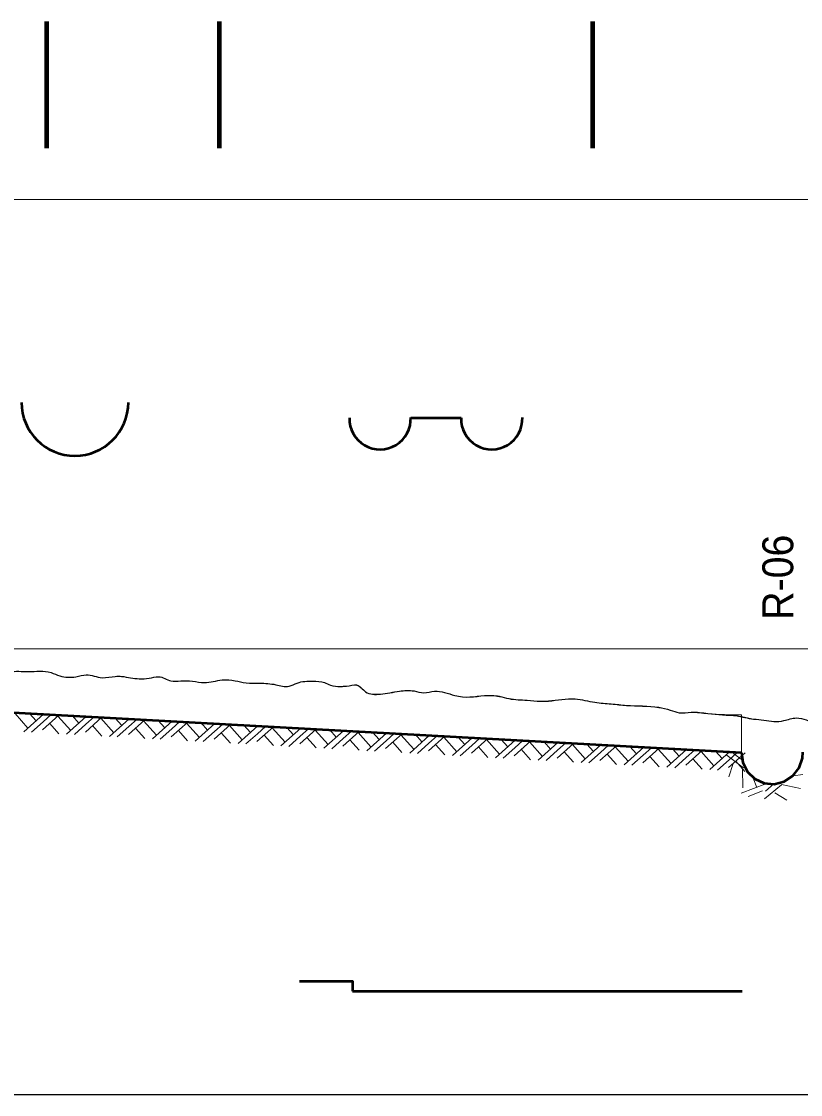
# Model space of a CAD drawing. Extents: x 8458 to 9360, y 19921 to 20366.
# Drawn here: x 8665.8 to 8766.6, y 20102.6 to 20241.4 of the extents above; entities that cross this region are included whole.
import ezdxf

# ---------------------------------------------------------------- set-up
doc = ezdxf.new("R2010")
doc.units = 0
doc.header["$LTSCALE"] = 1.2
doc.layers.add('5', color=7, linetype='Continuous', lineweight=13)

msp = doc.modelspace()

# ---------------------------------------------------------------- linework, layer by layer
at = {"layer": '5', "lineweight": 90}
for p, q in [((8669.04, 20225.05), (8669.04, 20241.43)), ((8691.42, 20225.05), (8691.42, 20241.43)), ((8739.72, 20225.05), (8739.72, 20241.43))]:
    msp.add_line(p, q, dxfattribs=at)
at = {"layer": '5'}
for p, q in [((8509.89, 20218.4), (9341.84, 20218.4)), ((8509.89, 20160.27), (9341.84, 20160.27)), ((8664.94, 20151.87), (8666.61, 20150)), ((8668.62, 20151.81), (8666.07, 20149.52)), ((8666.82, 20151.9), (8667.67, 20150.95)), ((8670.63, 20151.69), (8668.51, 20149.79)), ((8669.63, 20151.75), (8668.57, 20150.8)), ((8670.49, 20151.56), (8672.16, 20149.7)), ((8674.17, 20151.5), (8671.62, 20149.22)), ((8672.37, 20151.6), (8673.22, 20150.65)), ((8676.18, 20151.39), (8674.06, 20149.49)), ((8675.18, 20151.44), (8674.12, 20150.49)), ((8758.96, 20146.83), (8758.96, 20151.7)), ((8758.96, 20151.49), (8758.96, 20146.84)), ((8668.57, 20150.8), (8667.08, 20149.47)), ((8669.43, 20150.61), (8670.63, 20149.27)), ((8674.12, 20150.49), (8672.63, 20149.16)), ((8674.98, 20150.31), (8676.18, 20148.97)), ((8676.04, 20151.26), (8677.71, 20149.39)), ((8679.72, 20151.19), (8677.17, 20148.91)), ((8677.92, 20151.29), (8678.77, 20150.34)), ((8679.67, 20150.19), (8678.18, 20148.86)), ((8681.73, 20151.08), (8679.61, 20149.18)), ((8680.73, 20151.14), (8679.67, 20150.19)), ((8680.53, 20150), (8681.73, 20148.66)), ((8681.59, 20150.95), (8683.26, 20149.09)), ((8685.27, 20150.89), (8682.72, 20148.6)), ((8683.47, 20150.99), (8684.32, 20150.04)), ((8687.29, 20150.78), (8685.16, 20148.87)), ((8686.28, 20150.83), (8685.22, 20149.88)), ((8687.14, 20150.65), (8688.81, 20148.78)), ((8690.82, 20150.58), (8688.27, 20148.3)), ((8689.02, 20150.68), (8689.87, 20149.73)), ((8692.84, 20150.47), (8690.71, 20148.57)), ((8691.83, 20150.52), (8690.77, 20149.57)), ((8692.69, 20150.34), (8694.36, 20148.47)), ((8696.37, 20150.27), (8693.82, 20147.99)), ((8694.57, 20150.37), (8695.42, 20149.42)), ((8698.39, 20150.16), (8696.26, 20148.26)), ((8697.38, 20150.22), (8696.32, 20149.27)), ((8698.24, 20150.03), (8699.91, 20148.17)), ((8701.92, 20149.97), (8699.37, 20147.69)), ((8700.12, 20150.07), (8700.97, 20149.12)), ((8685.22, 20149.88), (8683.73, 20148.55)), ((8686.08, 20149.69), (8687.28, 20148.35)), ((8690.77, 20149.57), (8689.28, 20148.24)), ((8691.63, 20149.39), (8692.83, 20148.05)), ((8696.32, 20149.27), (8694.83, 20147.94)), ((8697.18, 20149.08), (8698.38, 20147.74)), ((8701.87, 20148.96), (8700.38, 20147.63)), ((8703.94, 20149.86), (8701.81, 20147.96)), ((8702.93, 20149.91), (8701.87, 20148.96)), ((8702.73, 20148.78), (8703.93, 20147.43)), ((8703.79, 20149.73), (8705.46, 20147.86)), ((8707.47, 20149.66), (8704.93, 20147.38)), ((8705.67, 20149.76), (8706.52, 20148.81)), ((8707.42, 20148.66), (8705.93, 20147.32)), ((8709.49, 20149.55), (8707.36, 20147.65)), ((8708.48, 20149.61), (8707.42, 20148.66)), ((8709.34, 20149.42), (8711.01, 20147.55)), ((8713.02, 20149.36), (8710.48, 20147.07)), ((8711.22, 20149.46), (8712.07, 20148.51)), ((8715.04, 20149.24), (8712.91, 20147.34)), ((8714.03, 20149.3), (8712.97, 20148.35)), ((8714.89, 20149.11), (8716.56, 20147.25)), ((8718.57, 20149.05), (8716.03, 20146.77)), ((8716.77, 20149.15), (8717.62, 20148.2)), ((8720.59, 20148.94), (8718.46, 20147.04)), ((8719.58, 20148.99), (8718.52, 20148.04)), ((8720.44, 20148.81), (8722.11, 20146.94)), ((8724.12, 20148.74), (8721.58, 20146.46)), ((8722.32, 20148.84), (8723.17, 20147.89)), ((8726.14, 20148.63), (8724.01, 20146.73)), ((8725.13, 20148.69), (8724.07, 20147.74)), ((8727.87, 20148.54), (8728.72, 20147.59)), ((8708.28, 20148.47), (8709.48, 20147.13)), ((8712.97, 20148.35), (8711.48, 20147.02)), ((8713.83, 20148.16), (8715.03, 20146.82)), ((8718.52, 20148.04), (8717.03, 20146.71)), ((8719.38, 20147.86), (8720.58, 20146.52)), ((8724.07, 20147.74), (8722.58, 20146.41)), ((8724.93, 20147.55), (8726.13, 20146.21)), ((8725.99, 20148.5), (8727.66, 20146.64)), ((8729.67, 20148.44), (8727.13, 20146.16)), ((8729.62, 20147.43), (8728.13, 20146.1)), ((8731.69, 20148.33), (8729.56, 20146.42)), ((8730.68, 20148.38), (8729.62, 20147.43)), ((8730.48, 20147.25), (8731.68, 20145.9)), ((8731.54, 20148.2), (8733.21, 20146.33)), ((8735.22, 20148.13), (8732.68, 20145.85)), ((8733.42, 20148.23), (8734.27, 20147.28)), ((8737.24, 20148.02), (8735.11, 20146.12)), ((8736.23, 20148.08), (8735.17, 20147.12)), ((8737.09, 20147.89), (8738.76, 20146.02)), ((8740.77, 20147.82), (8738.23, 20145.54)), ((8738.97, 20147.92), (8739.82, 20146.97)), ((8742.79, 20147.71), (8740.66, 20145.81)), ((8741.78, 20147.77), (8740.72, 20146.82)), ((8742.64, 20147.58), (8744.31, 20145.72)), ((8746.32, 20147.52), (8743.78, 20145.24)), ((8744.52, 20147.62), (8745.37, 20146.67)), ((8748.34, 20147.41), (8746.21, 20145.51)), ((8747.33, 20147.46), (8746.27, 20146.51)), ((8748.19, 20147.28), (8749.86, 20145.41)), ((8751.87, 20147.21), (8749.33, 20144.93)), ((8750.07, 20147.31), (8750.93, 20146.36)), ((8752.88, 20147.16), (8751.82, 20146.21)), ((8735.17, 20147.12), (8733.68, 20145.79)), ((8736.03, 20146.94), (8737.23, 20145.6)), ((8740.72, 20146.82), (8739.23, 20145.49)), ((8741.58, 20146.63), (8742.78, 20145.29)), ((8746.27, 20146.51), (8744.78, 20145.18)), ((8747.13, 20146.33), (8748.33, 20144.99)), ((8751.82, 20146.21), (8750.33, 20144.87)), ((8753.89, 20147.1), (8751.76, 20145.2)), ((8752.68, 20146.02), (8753.88, 20144.68)), ((8753.74, 20146.97), (8755.41, 20145.1)), ((8757.43, 20146.91), (8754.88, 20144.62)), ((8755.62, 20147.01), (8756.48, 20146.06)), ((8757.37, 20145.9), (8755.88, 20144.57)), ((8759.23, 20144.84), (8756.96, 20146.57)), ((8759.44, 20146.8), (8757.31, 20144.89)), ((8758.43, 20146.85), (8757.37, 20145.9)), ((8759.1, 20145.84), (8757.96, 20146.7)), ((8757.91, 20145.41), (8757.36, 20143.7)), ((8758.23, 20145.71), (8759.43, 20144.37)), ((8759.09, 20144.78), (8759.14, 20142.28)), ((8760.5, 20143.52), (8760.95, 20142.33)), ((8765.65, 20143.83), (8766.91, 20144)), ((8762.14, 20142.78), (8758.94, 20141.57)), ((8761.72, 20141.86), (8759.86, 20141.16)), ((8764.17, 20142.67), (8761.98, 20140.85)), ((8763.17, 20142.77), (8762.07, 20141.85)), ((8763.31, 20141.6), (8764.86, 20140.67)), ((8764.15, 20142.69), (8766.6, 20142.16))]:
    msp.add_line(p, q, dxfattribs=at)
at = {"layer": '5', "lineweight": 53}
for p, q in [((8716.17, 20190.15), (8722.68, 20190.14)), ((8607.57, 20155.17), (8758.96, 20146.82)), ((8607.57, 20155.17), (8758.96, 20146.82)), ((8708.62, 20115.95), (8759.06, 20115.95))]:
    msp.add_line(p, q, dxfattribs=at)
at = {"layer": '5', "lineweight": 25}
msp.add_line((8509.89, 20102.58), (9341.84, 20102.58), dxfattribs=at)
at = {"layer": '5'}
for points in [[(8607.57, 20158.92), (8607.57, 20155.18), (8758.96, 20146.83)], [(8758.96, 20146.84), (8759.14, 20145.53), (8759.74, 20144.35), (8760.7, 20143.43), (8761.91, 20142.88), (8763.23, 20142.76), (8764.51, 20143.08), (8765.62, 20143.8), (8766.43, 20144.85), (8766.86, 20146.1), (8766.9, 20146.9)]]:
    msp.add_lwpolyline(points, dxfattribs=at)
at = {"layer": '5', "lineweight": 53}
for points in [[(8758.96, 20146.84), (8759.14, 20145.53), (8759.74, 20144.35), (8760.7, 20143.43), (8761.91, 20142.88), (8763.23, 20142.76), (8764.51, 20143.08), (8765.62, 20143.8), (8766.43, 20144.85), (8766.86, 20146.1), (8766.9, 20146.9)], [(8758.96, 20146.84), (8759.14, 20145.53), (8759.74, 20144.35), (8760.7, 20143.43), (8761.91, 20142.88), (8763.23, 20142.76), (8764.51, 20143.08), (8765.62, 20143.8), (8766.43, 20144.85), (8766.86, 20146.1), (8766.9, 20146.9)], [(8701.77, 20117.26), (8708.62, 20117.26), (8708.62, 20115.95)]]:
    msp.add_lwpolyline(points, dxfattribs=at)
for centre, radius, start, end in [((8672.69, 20192.15), 6.92, 180.1681, 359.8318), ((8712.2, 20190.02), 3.97, 178.1436, 2.5541), ((8726.65, 20190.02), 3.97, 178.3116, 2.5541)]:
    msp.add_arc(centre, radius, start, end, dxfattribs=at)
at = {"layer": '5', "lineweight": 25}
for points in [[(8657.25, 20157.29), (8659.55, 20157.07), (8663.28, 20157.14), (8664.2, 20157.29), (8666.66, 20157.32), (8669.6, 20157.17), (8670.75, 20156.75), (8672.82, 20156.64), (8674.17, 20156.88), (8676.24, 20156.52), (8677.92, 20156.68), (8678.74, 20156.69), (8679.9, 20156.48), (8681.02, 20156.38), (8682.29, 20156.45), (8683.53, 20156.65), (8685.12, 20156.11), (8686.39, 20156.1), (8687.93, 20156.06), (8689.45, 20155.88), (8691.76, 20156.22), (8693.43, 20156.13), (8694.84, 20155.86), (8696.63, 20155.81), (8698.7, 20155.61), (8700.42, 20155.42), (8701.46, 20155.82), (8703.52, 20156.07), (8704.99, 20155.89), (8705.78, 20155.55), (8707.05, 20155.38), (8707.61, 20155.41)], [(8707.43, 20155.4), (8707.87, 20155.42), (8709.19, 20155.57), (8710.32, 20154.69), (8712.23, 20154.39), (8714.7, 20154.77), (8716.59, 20154.8), (8717.86, 20154.56), (8719.24, 20154.77), (8721.86, 20154.22), (8722.87, 20154.04), (8726.65, 20154.22), (8727.67, 20154.1), (8728.87, 20153.81), (8731.25, 20153.6), (8732.97, 20153.47), (8734, 20153.5), (8737.43, 20153.77), (8740.01, 20153.33), (8742.13, 20153.12), (8744.1, 20152.94), (8748.26, 20152.68), (8749.76, 20152.33), (8750.92, 20151.98), (8752.45, 20152.04), (8754.64, 20151.88), (8758.42, 20151.6)], [(8758.3, 20151.62), (8760.54, 20151.17), (8761.88, 20151.04), (8763.17, 20150.86), (8764.46, 20150.96), (8766.09, 20151.31), (8767.36, 20151.05), (8768.98, 20150.48), (8770.31, 20150.63), (8771.88, 20150.72), (8773.2, 20150.31), (8775.85, 20150.65), (8778.5, 20150.59), (8779.46, 20150.28), (8780.33, 20150.38), (8782.67, 20151.13), (8783.94, 20150.72), (8786.53, 20150.4), (8789.64, 20150.64), (8792.74, 20150.37), (8794.32, 20150.56), (8796.09, 20150.2), (8797.87, 20150.24), (8799.76, 20150.28), (8802.2, 20150.17), (8806.52, 20150.4), (8807.64, 20150.55), (8808.91, 20150.44), (8811.86, 20150.27), (8814, 20150.31), (8815.63, 20150.2), (8817.92, 20150.75), (8820.05, 20150.39), (8822.24, 20150.32), (8826.26, 20150.15), (8827.12, 20150.4), (8828.96, 20150.29), (8831.14, 20149.77), (8832.92, 20150.27), (8835.77, 20150.1), (8838.01, 20150.14), (8840.91, 20150.33), (8844.06, 20150.42), (8845.59, 20150.31), (8848.13, 20150.2), (8858.11, 20150.34)]]:
    msp.add_spline(points, degree=3, dxfattribs=at)
at = {"layer": '5'}
for points in [[(8707.61, 20155.41), (8707.05, 20155.38), (8705.78, 20155.55), (8704.99, 20155.89), (8703.52, 20156.07), (8701.46, 20155.82), (8700.42, 20155.42), (8698.7, 20155.61), (8696.63, 20155.81), (8694.84, 20155.86), (8693.43, 20156.13), (8691.76, 20156.22), (8689.45, 20155.88), (8687.93, 20156.06), (8686.39, 20156.1), (8685.12, 20156.11), (8683.53, 20156.65), (8682.29, 20156.45), (8681.02, 20156.38), (8679.9, 20156.48), (8678.74, 20156.69), (8677.92, 20156.68), (8676.24, 20156.52), (8674.17, 20156.88), (8672.82, 20156.64), (8670.75, 20156.75), (8669.6, 20157.17), (8666.66, 20157.32), (8664.2, 20157.29), (8663.28, 20157.14), (8659.55, 20157.07), (8657.29, 20157.29)], [(8758.96, 20151.7), (8754.64, 20151.89), (8752.45, 20152.05), (8750.92, 20151.99), (8749.75, 20152.33), (8748.26, 20152.69), (8744.1, 20152.94), (8742.13, 20153.13), (8740, 20153.33), (8737.43, 20153.77), (8733.99, 20153.51), (8732.96, 20153.48), (8731.25, 20153.6), (8728.87, 20153.82), (8727.67, 20154.11), (8726.65, 20154.23), (8722.86, 20154.04), (8721.86, 20154.22), (8719.24, 20154.77), (8717.85, 20154.56), (8716.59, 20154.8), (8714.7, 20154.77), (8712.23, 20154.4), (8710.31, 20154.7), (8709.19, 20155.58), (8707.87, 20155.42), (8707.61, 20155.41)], [(8858.21, 20150.32), (8848.13, 20150.2), (8845.59, 20150.31), (8844.06, 20150.42), (8840.91, 20150.33), (8838.01, 20150.14), (8835.77, 20150.1), (8832.92, 20150.27), (8831.14, 20149.77), (8828.96, 20150.29), (8827.12, 20150.4), (8826.26, 20150.15), (8822.24, 20150.32), (8820.05, 20150.39), (8817.92, 20150.75), (8815.63, 20150.2), (8814, 20150.31), (8811.86, 20150.27), (8808.91, 20150.44), (8807.64, 20150.55), (8806.52, 20150.4), (8802.2, 20150.17), (8799.76, 20150.28), (8797.87, 20150.24), (8796.09, 20150.2), (8794.32, 20150.56), (8792.74, 20150.37), (8789.64, 20150.64), (8786.53, 20150.4), (8783.94, 20150.72), (8782.67, 20151.13), (8780.33, 20150.38), (8779.46, 20150.28), (8778.5, 20150.59), (8775.85, 20150.65), (8773.2, 20150.31), (8771.88, 20150.72), (8770.31, 20150.63), (8768.98, 20150.48), (8767.36, 20151.05), (8766.09, 20151.31), (8764.46, 20150.96), (8763.17, 20150.86), (8761.88, 20151.04), (8760.54, 20151.17), (8758.96, 20151.49)]]:
    msp.add_spline(points, degree=3, dxfattribs=at)

# ---------------------------------------------------------------- texts
at = {"layer": '5', "width": 0.95}
msp.add_text('R-06', height=4, rotation=90, dxfattribs=at).set_placement((8765.68, 20164.01))

doc.saveas('drawing.dxf')
